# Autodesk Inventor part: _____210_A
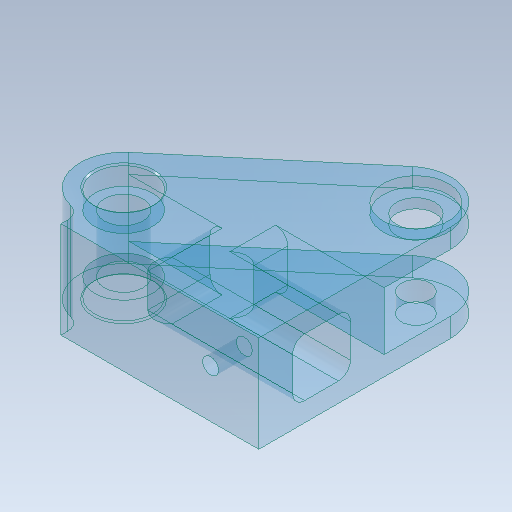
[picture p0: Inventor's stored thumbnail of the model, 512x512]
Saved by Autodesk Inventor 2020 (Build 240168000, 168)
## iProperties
Created: 2017-09
Part Number: _____210_A
Material: Polyéthylène, densité élevée
Document SubType Name: Modeling
Designer: bruno
Density: 0.952 g/cm^3
Appearance: Piscine intérieure
Mass: 19.5774 g
Surface Area: 97.5687 cm^2
Volume: 20.5645 cm^3
Sending System: SolidWorks 2016
Author: bruno
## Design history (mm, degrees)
feature "Importée1"
node "Solide1"
